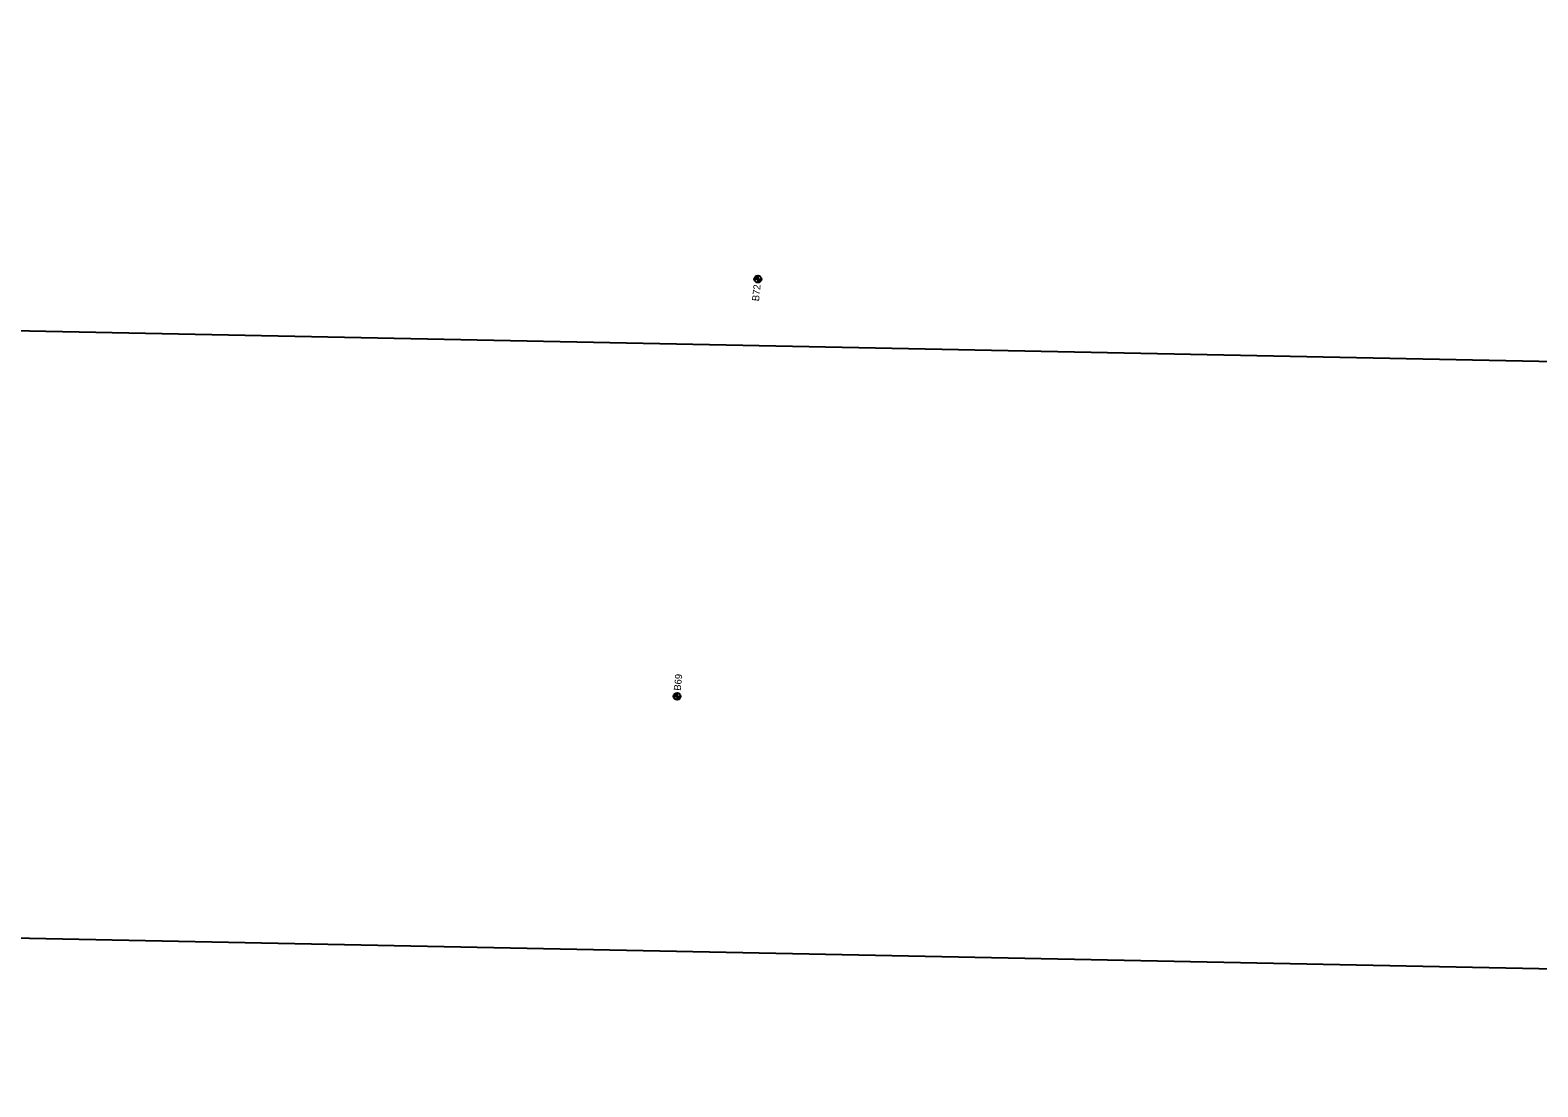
# Model space of a CAD drawing. Extents: x 335726 to 369746, y 119154 to 200788.
# Drawn here: x 358718 to 360859, y 168302 to 169803 of the extents above; entities that cross this region are included whole.
import ezdxf

# ---------------------------------------------------------------- set-up
doc = ezdxf.new("R2010")
doc.units = 0
for name, color, linetype in [('E_SOIL_BORE2 [KAPUR_CADDS_LEVELS]', 7, 'Continuous'), ('P_MARK', 7, 'Continuous'), ('PLT_Sheet_Border', 7, 'Continuous'), ('PLT_Sheet_Info', 7, 'Continuous')]:
    doc.layers.add(name, color=color, linetype=linetype)

msp = doc.modelspace()

# ---------------------------------------------------------------- linework, layer by layer
at = {"layer": 'P_MARK'}
for p, q in [((359746.5, 169449.5), (359756.5, 169449.5)), ((359751.5, 169454.5), (359751.5, 169444.5)), ((359631.8, 168856.8), (359641.8, 168856.8)), ((359636.8, 168861.8), (359636.8, 168851.8))]:
    msp.add_line(p, q, dxfattribs=at)
for centre in [(359751.5, 169449.5), (359636.8, 168856.8)]:
    msp.add_circle(centre, 5, dxfattribs=at)
for centre, radius, start, end in [((359751.5, 169449.5), 4.5, 89.9869, 179.9869), ((359751.5, 169449.5), 4, 89.9869, 179.9869), ((359751.5, 169449.5), 3.5, 89.9869, 179.9869), ((359751.5, 169449.5), 3, 89.9869, 179.9869), ((359751.5, 169449.5), 2.5, 89.9869, 179.9869), ((359751.5, 169449.5), 2, 89.9869, 179.9869), ((359751.5, 169449.5), 1.5, 89.9869, 179.9869), ((359751.5, 169449.5), 1, 89.9869, 179.9869), ((359751.5, 169449.5), 0.5, 89.9869, 179.9869), ((359751.5, 169449.5), 4.5, 269.9869, 359.9869), ((359751.5, 169449.5), 4, 269.9869, 359.9869), ((359751.5, 169449.5), 3.5, 269.9869, 359.9869), ((359751.5, 169449.5), 3, 269.9869, 359.9869), ((359751.5, 169449.5), 2.5, 269.9869, 359.9869), ((359751.5, 169449.5), 2, 269.9869, 359.9869), ((359751.5, 169449.5), 1.5, 269.9869, 359.9869), ((359751.5, 169449.5), 1, 269.9869, 359.9869), ((359751.5, 169449.5), 0.5, 269.9869, 359.9869), ((359636.8, 168856.8), 4.5, 89.9869, 179.9869), ((359636.8, 168856.8), 4, 89.9869, 179.9869), ((359636.8, 168856.8), 3.5, 89.9869, 179.9869), ((359636.8, 168856.8), 3, 89.9869, 179.9869), ((359636.8, 168856.8), 2.5, 89.9869, 179.9869), ((359636.8, 168856.8), 2, 89.9869, 179.9869), ((359636.8, 168856.8), 1.5, 89.9869, 179.9869), ((359636.8, 168856.8), 1, 89.9869, 179.9869), ((359636.8, 168856.8), 0.5, 89.9869, 179.9869), ((359636.8, 168856.8), 4.5, 269.9869, 359.9869), ((359636.8, 168856.8), 4, 269.9869, 359.9869), ((359636.8, 168856.8), 3.5, 269.9869, 359.9869), ((359636.8, 168856.8), 3, 269.9869, 359.9869), ((359636.8, 168856.8), 2.5, 269.9869, 359.9869), ((359636.8, 168856.8), 2, 269.9869, 359.9869), ((359636.8, 168856.8), 1.5, 269.9869, 359.9869), ((359636.8, 168856.8), 1, 269.9869, 359.9869), ((359636.8, 168856.8), 0.5, 269.9869, 359.9869)]:
    msp.add_arc(centre, radius, start, end, dxfattribs=at)
at = {"layer": 'PLT_Sheet_Border'}
msp.add_lwpolyline([(367976.5, 119528.9), (368976.2, 169168.9), (337482.6, 169803.1), (336482.9, 120163.2)], close=True, dxfattribs=at)
at = {"layer": 'PLT_Sheet_Info'}
msp.add_line((368209, 168321.6), (338215.1, 168925.7), dxfattribs=at)

# ---------------------------------------------------------------- texts
at = {"layer": 'E_SOIL_BORE2 [KAPUR_CADDS_LEVELS]'}
for s, p in [('B72', (359753.1, 169417.7)), ('B69', (359641.9, 168864.4))]:
    msp.add_text(s, height=10, rotation=84.1728, dxfattribs=at).set_placement(p)

doc.saveas('drawing.dxf')
